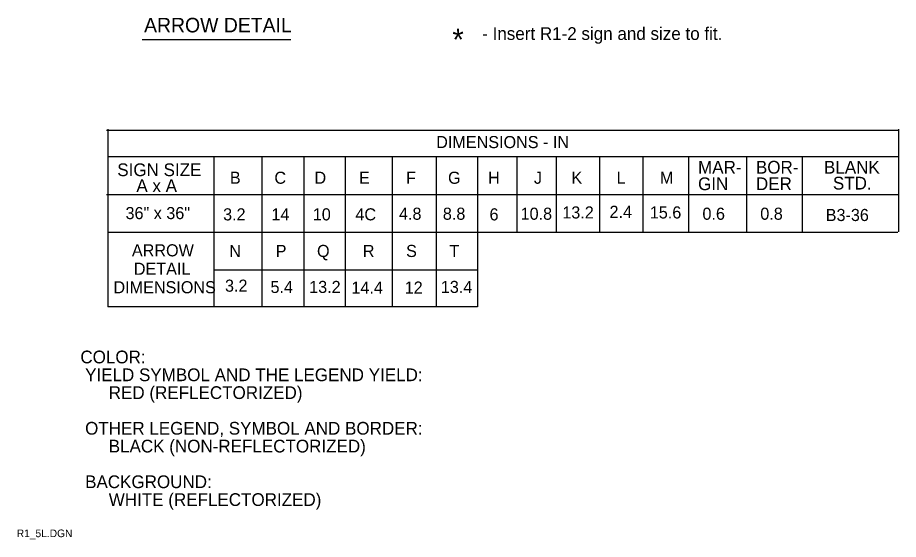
# Model space of a CAD drawing. Extents: x 0.013 to 0.186, y 0.004 to 0.259.
# Drawn here: x 0.0128 to 0.1859, y 0.0039 to 0.1064 of the extents above; entities that cross this region are included whole.
import ezdxf

# ---------------------------------------------------------------- set-up
doc = ezdxf.new("R2010")
doc.units = 0
doc.layers.add('1', color=7, linetype='Continuous')
doc.layers.add('3', color=7, linetype='Continuous')

msp = doc.modelspace()

# ---------------------------------------------------------------- linework, layer by layer
at = {"layer": '3'}
for p, q in [((0.03726216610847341, 0.10205351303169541), (0.06646818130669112, 0.10205351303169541)), ((0.03025, 0.08425), (0.18575, 0.08425)), ((0.030510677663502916, 0.08444028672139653), (0.030510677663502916, 0.04959498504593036)), ((0.18586708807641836, 0.08444028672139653), (0.18586708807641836, 0.06432524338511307)), ((0.18586708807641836, 0.07905550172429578), (0.030510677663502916, 0.07905550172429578)), ((0.051353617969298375, 0.07905550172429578), (0.051353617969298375, 0.04959498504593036)), ((0.15600656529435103, 0.07905550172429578), (0.15600656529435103, 0.06432524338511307)), ((0.16693973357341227, 0.07905550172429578), (0.16693973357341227, 0.06432524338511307)), ((0.03025, 0.07162500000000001), (0.18575, 0.07162500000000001)), ((0.0305, 0.06425), (0.18575, 0.06425)), ((0.051250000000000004, 0.056875), (0.10312500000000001, 0.056875)), ((0.10313567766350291, 0.04959498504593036), (0.030510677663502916, 0.04959498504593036))]:
    msp.add_line(p, q, dxfattribs=at)
for points in [[(0.06076067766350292, 0.07905550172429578), (0.06076067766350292, 0.04959498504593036)], [(0.06901067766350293, 0.07905550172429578), (0.06901067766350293, 0.04959498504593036)], [(0.07713567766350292, 0.07905550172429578), (0.07713567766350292, 0.04959498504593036)], [(0.08638567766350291, 0.07905550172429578), (0.08638567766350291, 0.04959498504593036)], [(0.09501067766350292, 0.07905550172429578), (0.09501067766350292, 0.04959498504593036)], [(0.10313567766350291, 0.07905550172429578), (0.10313567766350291, 0.04959498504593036)], [(0.11088567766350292, 0.07905550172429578), (0.11088567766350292, 0.06425)], [(0.11863567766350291, 0.07905550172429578), (0.11863567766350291, 0.06432524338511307)], [(0.1271587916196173, 0.07905550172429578), (0.1271587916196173, 0.06432524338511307)], [(0.1356819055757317, 0.07905550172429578), (0.1356819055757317, 0.06432524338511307)], [(0.14462161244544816, 0.07905550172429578), (0.14462161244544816, 0.06432524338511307)]]:
    msp.add_lwpolyline(points, dxfattribs=at)

# ---------------------------------------------------------------- texts
at = {"layer": '1'}
msp.add_text('*', height=0.00432, rotation=2, dxfattribs=at).set_placement((0.09833660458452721, 0.09986429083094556))
for s, height, p in [('- Insert R1-2 sign and size to fit.', 0.0024997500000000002, (0.1040866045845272, 0.10198929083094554)), ('COLOR:', 0.0024997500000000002, (0.025125, 0.03849825)), (' YIELD SYMBOL AND THE LEGEND YIELD:', 0.0024997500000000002, (0.025125, 0.0349985)), ('      RED (REFLECTORIZED)', 0.0024997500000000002, (0.025125, 0.03149874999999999)), (' OTHER LEGEND, SYMBOL AND BORDER:', 0.0024997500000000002, (0.025125, 0.024499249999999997)), ('      BLACK (NON-REFLECTORIZED)', 0.0024997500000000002, (0.025125, 0.020999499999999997)), (' BACKGROUND:', 0.0024997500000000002, (0.025125, 0.014)), ('      WHITE (REFLECTORIZED)', 0.0024997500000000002, (0.025125, 0.010500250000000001)), ('R1_5L.DGN', 0.0015, (0.012625, 0.004375))]:
    msp.add_text(s, height=height, dxfattribs=at).set_placement(p)
at = {"layer": '3'}
for s, height, p in [('ARROW DETAIL', 0.00285, (0.037643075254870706, 0.10347572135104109)), ('DIMENSIONS - IN', 0.0023752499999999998, (0.09504229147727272, 0.08075)), ('MAR-', 0.0024997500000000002, (0.1465, 0.07575)), ('BOR-', 0.0024997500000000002, (0.15787500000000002, 0.07575)), ('BLANK', 0.0024997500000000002, (0.17125, 0.07575)), ('SIGN SIZE', 0.0024997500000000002, (0.032375, 0.07525)), ('C', 0.0023752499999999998, (0.06325, 0.07375)), ('G', 0.0023752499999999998, (0.097375, 0.07375)), ('A x A', 0.0024997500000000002, (0.036125, 0.072125)), ('B', 0.0023752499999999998, (0.0545, 0.07375)), ('D', 0.0023752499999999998, (0.07112500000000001, 0.07375)), ('E', 0.0023752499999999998, (0.079875, 0.07375)), ('F', 0.0023752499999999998, (0.089125, 0.07375)), ('H', 0.0023752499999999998, (0.10525, 0.07375)), ('J', 0.0023752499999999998, (0.11425, 0.07375)), ('K', 0.0023752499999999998, (0.121625, 0.07375)), ('L', 0.0023752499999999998, (0.1305, 0.07375)), ('M', 0.0023752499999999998, (0.139, 0.07375)), ('GIN', 0.0024997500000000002, (0.1465, 0.0725)), ('DER', 0.0024997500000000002, (0.15787500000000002, 0.0725)), ('STD.', 0.0024997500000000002, (0.17300000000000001, 0.072625)), ('13.2', 0.0023752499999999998, (0.11982520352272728, 0.06693737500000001)), ('2.4', 0.0023752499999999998, (0.12910699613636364, 0.06706237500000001)), ('15.6', 0.0023752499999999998, (0.13702373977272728, 0.06693737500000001)), ('36" x 36"', 0.0023752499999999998, (0.033995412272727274, 0.06681237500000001)), ('3.2', 0.0023752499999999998, (0.05316997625, 0.06656237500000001)), ('14', 0.0023752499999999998, (0.06266578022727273, 0.06656237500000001)), ('10', 0.0023752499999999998, (0.07079725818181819, 0.06656237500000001)), ('4C', 0.0023752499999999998, (0.07916457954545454, 0.06656237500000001)), ('4.8', 0.0023752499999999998, (0.08773055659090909, 0.06668737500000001)), ('8.8', 0.0023752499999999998, (0.0963555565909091, 0.06668737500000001)), ('6', 0.0023752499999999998, (0.10552206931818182, 0.06656237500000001)), ('10.8', 0.0023752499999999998, (0.11163264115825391, 0.06668737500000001)), ('0.6', 0.0023752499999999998, (0.14736851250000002, 0.06668737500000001)), ('0.8', 0.0023752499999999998, (0.1587305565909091, 0.06668737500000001)), ('B3-36', 0.0023752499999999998, (0.171589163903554, 0.066437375)), ('ARROW', 0.0023752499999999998, (0.035250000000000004, 0.059500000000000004)), ('N', 0.0023752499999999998, (0.054375, 0.059375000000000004)), ('P', 0.0023752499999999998, (0.0635, 0.059375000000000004)), ('Q', 0.0023752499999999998, (0.07162500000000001, 0.059375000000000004)), ('R', 0.0023752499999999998, (0.080625, 0.059375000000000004)), ('S', 0.0023752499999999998, (0.089125, 0.059375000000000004)), ('T', 0.0023752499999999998, (0.097625, 0.059375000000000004)), ('DETAIL', 0.0023752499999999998, (0.035625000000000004, 0.055875)), ('DIMENSIONS', 0.0023752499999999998, (0.031625, 0.05225)), ('3.2', 0.0023752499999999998, (0.05354497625, 0.052562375)), ('5.4', 0.0023752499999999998, (0.062481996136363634, 0.052312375)), ('13.2', 0.0023752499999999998, (0.07008597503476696, 0.052312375)), ('14.4', 0.0023752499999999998, (0.0783872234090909, 0.052187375)), ('12', 0.0023752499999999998, (0.0888537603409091, 0.052187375)), ('13.4', 0.0023752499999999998, (0.09595601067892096, 0.052312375))]:
    msp.add_text(s, height=height, dxfattribs=at).set_placement(p)

doc.saveas('drawing.dxf')
